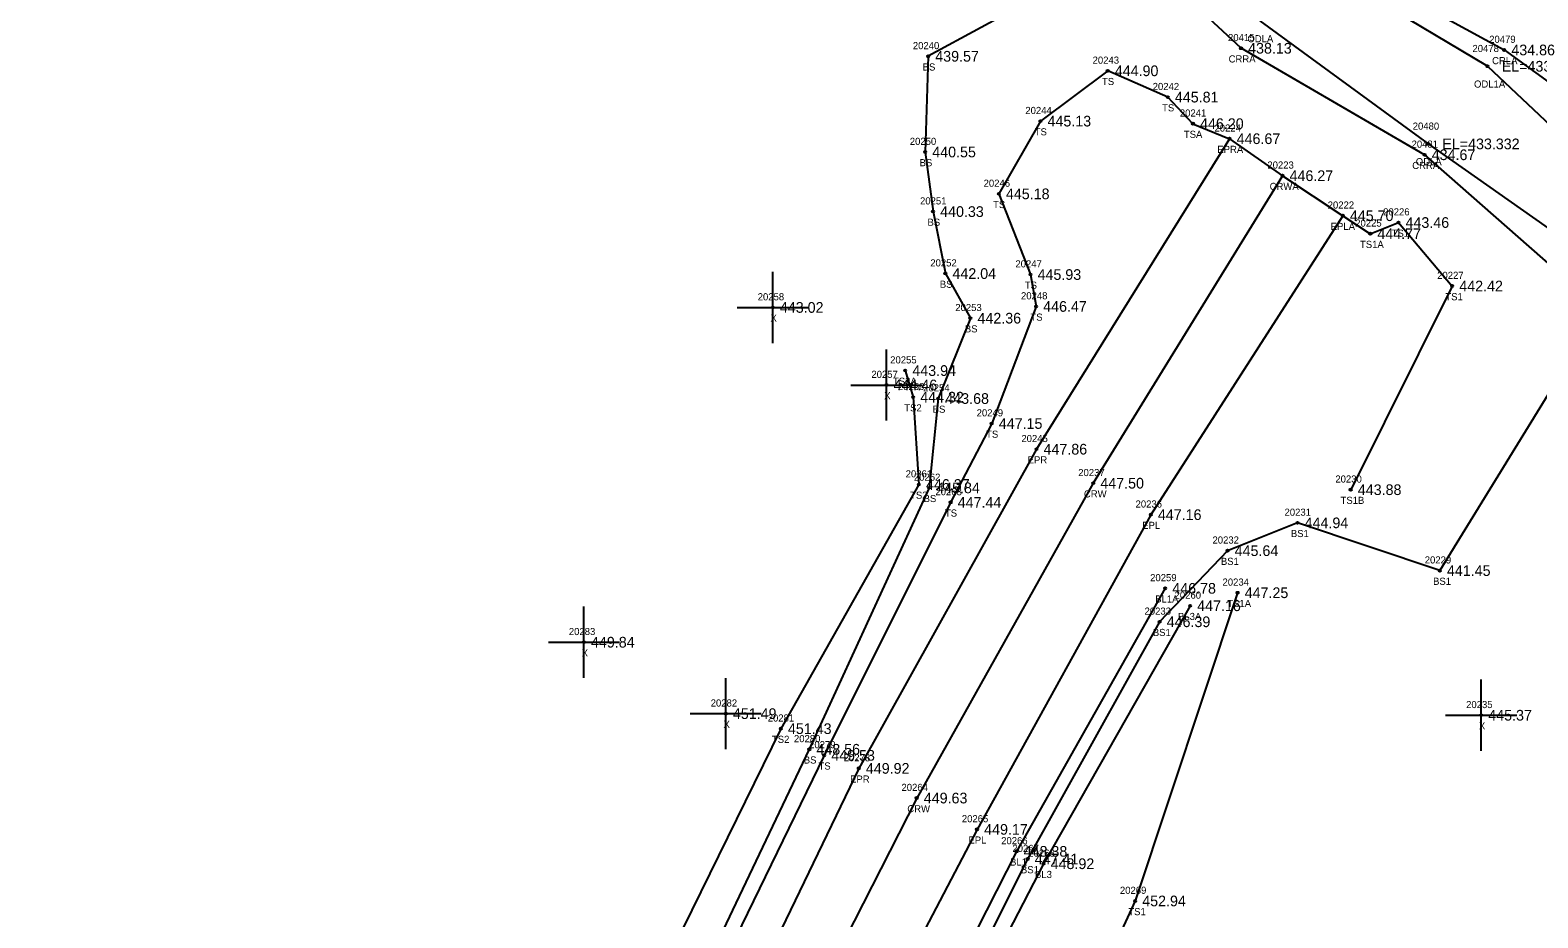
# Model space of a CAD drawing. Extents: x 1763022 to 1764007, y 824123 to 825394.
# Drawn here: x 1763289.5 to 1763501.5, y 824690.9 to 824815.6 of the extents above; entities that cross this region are included whole.
import ezdxf

# ---------------------------------------------------------------- set-up
doc = ezdxf.new("R2010")
doc.units = 0
for name, color, linetype in [('RD_DTM_BkLn1', 7, 'Continuous'), ('RD_DTM_BkLn2', 7, 'Continuous'), ('RD_DTM_BkLn_txCode', 7, 'Continuous'), ('RD_EX_H2O', 7, 'Continuous'), ('RD_EX_H2O_txCode', 7, 'Continuous'), ('RD_EX_Misc', 7, 'Continuous'), ('RD_EX_Misc_txCode', 7, 'Continuous'), ('RD_EX_Road', 7, 'Continuous'), ('RD_EX_Road_txCode', 7, 'Continuous'), ('RD_EX_TX_H2O_ELEV', 7, 'Continuous'), ('RD_EX_TX_Misc_ELEV', 7, 'Continuous'), ('RD_EX_TX_Road_ELEV', 7, 'Continuous'), ('RD_HC_Survey_ELEV', 7, 'Continuous'), ('RD_HC_Survey_txCode', 7, 'Continuous'), ('RD_SMD_Locator', 7, 'Continuous')]:
    doc.layers.add(name, color=color, linetype=linetype)

msp = doc.modelspace()

# ---------------------------------------------------------------- linework, layer by layer
at = {"layer": 'RD_DTM_BkLn1'}
for points in [[(1763465.6, 824795.18), (1763438.99, 824751.97), (1763414.16, 824707.73), (1763391.5, 824663.21), (1763370.27, 824618.19), (1763351.39, 824571.8), (1763333.36, 824525.39), (1763297, 824431.97), (1763261.49, 824337.79), (1763225.86, 824243.32), (1763189.96, 824148.95)], [(1763449.11, 824737.2), (1763428.21, 824700.24), (1763405.61, 824655.82), (1763384.69, 824612.58), (1763368.75, 824575.91)], [(1763452.61, 824734.75), (1763432, 824698.5), (1763409.25, 824654.57), (1763387.93, 824610.55), (1763372.47, 824573.42), (1763370.6, 824574.02), (1763368.75, 824575.91)]]:
    msp.add_lwpolyline(points, dxfattribs=at)
at = {"layer": 'RD_DTM_BkLn2'}
for points in [[(1763437.34, 824834), (1763430.66, 824820.06), (1763415.77, 824811.96), (1763415.35, 824798.51), (1763416.46, 824790.14), (1763418.19, 824781.43), (1763421.71, 824775.16), (1763417.19, 824763.87), (1763415.91, 824751.32), (1763399.06, 824714.58), (1763377.03, 824668.46), (1763355.81, 824623.79), (1763331.1, 824577.59), (1763312.25, 824532.84), (1763306.13, 824522.15), (1763306.75, 824510.59), (1763289.07, 824468.95), (1763279.57, 824438.1), (1763246.06, 824343.25), (1763209.87, 824247.25), (1763175.28, 824154.06)], [(1763453.01, 824802.49), (1763449.47, 824806.22), (1763441.02, 824809.92), (1763431.56, 824802.85), (1763425.71, 824792.63), (1763430.16, 824781.29), (1763430.95, 824776.81), (1763424.71, 824760.36), (1763418.93, 824749.28), (1763401.15, 824713.73), (1763378.81, 824667.77), (1763358.94, 824622.73), (1763337, 824576.46), (1763318.92, 824530.87), (1763314.75, 824518.63), (1763292.84, 824467.34), (1763282.85, 824437.24), (1763248.29, 824342.54), (1763211.77, 824246.85), (1763177.66, 824153.22)], [(1763477.95, 824787.03), (1763481.91, 824788.6), (1763489.47, 824779.68), (1763475.2, 824751.06)], [(1763510.31, 824776.41), (1763487.73, 824739.69), (1763467.72, 824746.4), (1763457.88, 824742.49), (1763448.32, 824732.5), (1763429.76, 824699.16), (1763407.64, 824655.12), (1763386.68, 824612.12), (1763370.96, 824575.87)], [(1763412.55, 824767.8), (1763413.66, 824764.06), (1763414.47, 824751.79), (1763395.05, 824717.48), (1763372.53, 824671.63), (1763352.41, 824624.78), (1763336.93, 824590.86)], [(1763459.29, 824736.58), (1763444.88, 824693.27), (1763423.62, 824647.11), (1763406.14, 824602.89), (1763396.88, 824581.15), (1763372.47, 824573.42)]]:
    msp.add_lwpolyline(points, dxfattribs=at)
at = {"layer": 'RD_EX_H2O'}
for p, q in [((1763469.64, 824827.68), (1763496.79, 824812.85)), ((1763494.44, 824810.56), (1763468.68, 824825.92)), ((1763462.4, 824816.93), (1763486.08, 824799.65)), ((1763485.59, 824798.12), (1763459.77, 824813.09))]:
    msp.add_line(p, q, dxfattribs=at)
for points in [[(1763459.77, 824813.09), (1763437.3, 824833.98), (1763421.73, 824846.89), (1763391.2, 824896.67), (1763313.16, 824962.88), (1763227.9, 824997.52), (1763208.46, 824998.22), (1763114.18, 824952.92), (1763092.86, 824935.95), (1763064.35, 824852.13)], [(1763496.79, 824812.85), (1763505.69, 824806.42), (1763507.16, 824805.23), (1763521.58, 824789.49), (1763543.54, 824765.51), (1763572.14, 824752.09), (1763662.42, 824704.48), (1763697.56, 824670.47), (1763707.93, 824630.76), (1763723.52, 824595.87), (1763766.82, 824582.67), (1763818.29, 824585.49), (1763920.08, 824604.11)], [(1763494.44, 824810.56), (1763519.46, 824787), (1763539.48, 824759.37), (1763565.01, 824743.23), (1763659.79, 824699.35), (1763693.94, 824667), (1763705.55, 824629.75), (1763723.44, 824593.51), (1763767.2, 824575.02), (1763820.02, 824582.79), (1763920.83, 824600.99)], [(1763486.08, 824799.65), (1763514.15, 824779.95), (1763533.52, 824748.31), (1763547.12, 824731.03), (1763648.42, 824679.07), (1763662.67, 824682.83), (1763683.5, 824662.48), (1763694.46, 824627.33), (1763694.82, 824601.41), (1763712.85, 824586.53), (1763766.86, 824564.42), (1763816.87, 824572.85), (1763926.33, 824585.82)], [(1763485.59, 824798.12), (1763510.28, 824776.41), (1763530.73, 824746.57), (1763546.51, 824728.76), (1763647.95, 824677.16), (1763661.46, 824680.21), (1763679.15, 824659.29), (1763688.38, 824626.34), (1763689.04, 824599.45), (1763710.73, 824574.27), (1763740.3, 824562), (1763762.69, 824555.26), (1763820.3, 824563.65), (1763926.69, 824582.3)]]:
    msp.add_lwpolyline(points, dxfattribs=at)
at = {"layer": 'RD_EX_Misc'}
for p, q in [((1763393.92, 824771.67), (1763393.92, 824781.67)), ((1763388.92, 824776.67), (1763398.92, 824776.67)), ((1763409.91, 824760.77), (1763409.91, 824770.77)), ((1763404.91, 824765.77), (1763414.91, 824765.77)), ((1763367.36, 824724.63), (1763367.36, 824734.63)), ((1763362.36, 824729.63), (1763372.36, 824729.63)), ((1763387.31, 824714.59), (1763387.31, 824724.59)), ((1763493.55, 824714.37), (1763493.55, 824724.37)), ((1763382.31, 824719.59), (1763392.31, 824719.59)), ((1763488.55, 824719.37), (1763498.55, 824719.37))]:
    msp.add_line(p, q, dxfattribs=at)
at = {"layer": 'RD_EX_Road'}
for points in [[(1763453.01, 824802.49), (1763458.16, 824800.38), (1763465.6, 824795.18), (1763474.08, 824789.56), (1763477.95, 824787.03)], [(1763458.16, 824800.38), (1763431, 824756.75), (1763406.01, 824711.9), (1763384.24, 824666.74), (1763362.81, 824620.84), (1763342.79, 824575), (1763324.89, 824528.78), (1763288.3, 824435.22), (1763252.09, 824341.05), (1763216.31, 824245.88), (1763180.37, 824152.33)], [(1763474.08, 824789.56), (1763447.08, 824747.55), (1763422.65, 824703.33), (1763399.6, 824659.26), (1763379.31, 824614.36), (1763364.49, 824579.4), (1763364.49, 824579.4), (1763359.36, 824568.52), (1763347.68, 824537.95), (1763341.79, 824522.26), (1763305.94, 824428.62), (1763270.17, 824334.76), (1763235.03, 824239.84), (1763198.43, 824144.73)]]:
    msp.add_lwpolyline(points, dxfattribs=at)
at = {"layer": 'RD_SMD_Locator'}
for centre in [(1763415.77, 824811.96), (1763459.77, 824813.09), (1763496.79, 824812.85), (1763441.02, 824809.92), (1763494.44, 824810.56), (1763449.47, 824806.22), (1763431.56, 824802.85), (1763453.01, 824802.49), (1763415.35, 824798.51), (1763458.16, 824800.38), (1763486.08, 824799.65), (1763485.59, 824798.12), (1763465.6, 824795.18), (1763425.71, 824792.63), (1763416.46, 824790.14), (1763474.08, 824789.56), (1763481.91, 824788.6), (1763477.95, 824787.03), (1763418.19, 824781.43), (1763430.16, 824781.29), (1763489.47, 824779.68), (1763393.92, 824776.67), (1763430.95, 824776.81), (1763421.71, 824775.16), (1763412.55, 824767.8), (1763409.91, 824765.77), (1763413.66, 824764.06), (1763417.19, 824763.87), (1763424.71, 824760.36), (1763431, 824756.75), (1763438.99, 824751.97), (1763414.47, 824751.79), (1763415.91, 824751.32), (1763475.2, 824751.06), (1763418.93, 824749.28), (1763447.08, 824747.55), (1763467.72, 824746.4), (1763457.88, 824742.49), (1763487.73, 824739.69), (1763449.11, 824737.2), (1763459.29, 824736.58), (1763452.61, 824734.75), (1763448.32, 824732.5), (1763367.36, 824729.63), (1763387.31, 824719.59), (1763493.55, 824719.37), (1763395.05, 824717.48), (1763399.06, 824714.58), (1763401.15, 824713.73), (1763406.01, 824711.9), (1763414.16, 824707.73), (1763422.65, 824703.33), (1763428.21, 824700.24), (1763429.76, 824699.16), (1763432, 824698.5), (1763444.88, 824693.27)]:
    msp.add_circle(centre, 0.15, dxfattribs=at)

# ---------------------------------------------------------------- texts
at = {"layer": 'RD_DTM_BkLn_txCode'}
for s, p in [('20240', (1763413.62, 824812.96)), ('20243', (1763438.9, 824810.92)), ('BS', (1763415, 824809.96)), ('TS', (1763440.22, 824807.92)), ('20242', (1763447.35, 824807.22)), ('TS', (1763448.67, 824804.22)), ('20244', (1763429.44, 824803.85)), ('20241', (1763451.17, 824803.49)), ('TS', (1763430.76, 824800.85)), ('TSA', (1763451.73, 824800.49)), ('20250', (1763413.19, 824799.51)), ('BS', (1763414.57, 824796.51)), ('20246', (1763423.57, 824793.63)), ('20251', (1763414.63, 824791.14)), ('TS', (1763424.91, 824790.63)), ('20226', (1763479.76, 824789.6)), ('BS', (1763415.68, 824788.14)), ('20225', (1763475.83, 824788.03)), ('TS1A', (1763476.5, 824785.03)), ('TS1', (1763480.95, 824786.6)), ('20252', (1763416.07, 824782.43)), ('20247', (1763428.04, 824782.29)), ('20227', (1763487.36, 824780.68)), ('BS', (1763417.41, 824779.43)), ('TS', (1763429.37, 824779.29)), ('20248', (1763428.83, 824777.81)), ('TS1', (1763488.51, 824777.68)), ('20253', (1763419.59, 824776.16)), ('TS', (1763430.16, 824774.81)), ('BS', (1763420.93, 824773.16)), ('20255', (1763410.43, 824768.8)), ('TS2A', (1763410.82, 824765.8)), ('20256', (1763411.51, 824765.06)), ('20254', (1763415.07, 824764.87)), ('TS2', (1763412.41, 824762.06)), ('BS', (1763416.41, 824761.87)), ('20249', (1763422.59, 824761.36)), ('TS', (1763423.92, 824758.36)), ('20261', (1763412.61, 824752.79)), ('20262', (1763413.77, 824752.32)), ('20230', (1763473.04, 824752.06)), ('TS2', (1763413.23, 824749.79)), ('BS', (1763415.13, 824749.32)), ('20263', (1763416.79, 824750.28)), ('TS1B', (1763473.77, 824749.06)), ('TS', (1763418.13, 824747.28)), ('20231', (1763465.89, 824747.4)), ('20232', (1763455.76, 824743.49)), ('BS1', (1763466.78, 824744.4)), ('BS1', (1763456.94, 824740.49)), ('20229', (1763485.61, 824740.69)), ('20259', (1763446.99, 824738.2)), ('20234', (1763457.17, 824737.58)), ('BS1', (1763486.78, 824737.69)), ('BL1A', (1763447.7, 824735.2)), ('20260', (1763450.43, 824735.75)), ('TS1A', (1763457.84, 824734.58)), ('20233', (1763446.2, 824733.5)), ('BL3A', (1763450.91, 824732.75)), ('BS1', (1763447.37, 824730.5)), ('20281', (1763393.21, 824718.48)), ('TS2', (1763393.8, 824715.48)), ('20280', (1763396.9, 824715.58)), ('20279', (1763399.03, 824714.73)), ('BS', (1763398.28, 824712.58)), ('TS', (1763400.35, 824711.73)), ('20266', (1763426.04, 824701.24)), ('20267', (1763427.62, 824700.16)), ('BL1', (1763427.29, 824698.24)), ('20268', (1763429.86, 824699.5)), ('BS1', (1763428.82, 824697.16)), ('BL3', (1763430.8, 824696.5)), ('20269', (1763442.74, 824694.27)), ('TS1', (1763443.92, 824691.27))]:
    msp.add_text(s, height=1, dxfattribs=at).set_placement(p)
at = {"layer": 'RD_EX_H2O_txCode'}
for s, p in [('20415', (1763457.94, 824814.09)), ('ODLA', (1763460.67, 824813.93)), ('20478', (1763492.32, 824812.56)), ('20479', (1763494.67, 824813.85)), ('CRRA', (1763458.03, 824811.09)), ('CRLA', (1763495.08, 824810.85)), ('ODL1A', (1763492.54, 824807.56)), ('20480', (1763483.92, 824801.65)), ('20481', (1763483.76, 824799.12)), ('CRRA', (1763483.85, 824796.12)), ('ODLA', (1763484.35, 824796.65))]:
    msp.add_text(s, height=1, dxfattribs=at).set_placement(p)
at = {"layer": 'RD_EX_Misc_txCode'}
for s, p in [('20258', (1763391.8, 824777.67)), ('X', (1763393.6, 824774.67)), ('20257', (1763407.79, 824766.77)), ('X', (1763409.59, 824763.77)), ('20283', (1763365.24, 824730.63)), ('X', (1763367.05, 824727.63)), ('20282', (1763385.19, 824720.59)), ('20235', (1763491.43, 824720.37)), ('X', (1763386.99, 824717.59)), ('X', (1763493.23, 824717.37))]:
    msp.add_text(s, height=1, dxfattribs=at).set_placement(p)
at = {"layer": 'RD_EX_Road_txCode'}
for s, p in [('20224', (1763456.04, 824801.38)), ('EPRA', (1763456.44, 824798.38)), ('20222', (1763471.96, 824790.56)), ('EPLA', (1763472.38, 824787.56)), ('20245', (1763428.88, 824757.75)), ('EPR', (1763429.77, 824754.75)), ('20236', (1763444.94, 824748.55)), ('EPL', (1763445.87, 824745.55)), ('20278', (1763403.9, 824712.9)), ('EPR', (1763404.79, 824709.9)), ('20265', (1763420.51, 824704.33)), ('EPL', (1763421.44, 824701.33))]:
    msp.add_text(s, height=1, dxfattribs=at).set_placement(p)
at = {"layer": 'RD_EX_TX_H2O_ELEV'}
for s, p in [('438.13', (1763460.77, 824812.34)), ('434.86', (1763497.79, 824812.1)), ('EL=433.437', (1763496.44, 824809.81)), ('434.67', (1763486.59, 824797.37)), ('EL=433.332', (1763488.08, 824798.9))]:
    msp.add_text(s, height=1.5, dxfattribs=at).set_placement(p)
at = {"layer": 'RD_EX_TX_Misc_ELEV'}
for s, p in [('439.57', (1763416.77, 824811.21)), ('444.90', (1763442.02, 824809.17)), ('445.81', (1763450.47, 824805.47)), ('445.13', (1763432.56, 824802.1)), ('446.20', (1763454.01, 824801.74)), ('440.55', (1763416.35, 824797.76)), ('445.18', (1763426.71, 824791.88)), ('440.33', (1763417.46, 824789.39)), ('443.46', (1763482.91, 824787.85)), ('444.77', (1763478.95, 824786.28)), ('442.04', (1763419.19, 824780.68)), ('445.93', (1763431.16, 824780.54)), ('442.42', (1763490.47, 824778.93)), ('443.02', (1763394.92, 824775.92)), ('446.47', (1763431.95, 824776.06)), ('442.36', (1763422.71, 824774.41)), ('443.94', (1763413.55, 824767.05)), ('444.46', (1763410.91, 824765.02)), ('444.32', (1763414.66, 824763.31)), ('443.68', (1763418.19, 824763.12)), ('447.15', (1763425.71, 824759.61)), ('446.37', (1763415.47, 824751.04)), ('445.84', (1763416.91, 824750.57)), ('447.44', (1763419.93, 824748.53)), ('443.88', (1763476.2, 824750.31)), ('444.94', (1763468.72, 824745.65)), ('445.64', (1763458.88, 824741.74)), ('441.45', (1763488.73, 824738.94)), ('446.78', (1763450.11, 824736.45)), ('447.25', (1763460.29, 824735.83)), ('447.16', (1763453.61, 824734)), ('446.39', (1763449.32, 824731.75)), ('449.84', (1763368.36, 824728.88)), ('451.49', (1763388.31, 824718.84)), ('451.43', (1763396.05, 824716.73)), ('445.37', (1763494.55, 824718.62)), ('448.56', (1763400.06, 824713.83)), ('449.53', (1763402.15, 824712.98)), ('448.38', (1763429.21, 824699.49)), ('447.41', (1763430.76, 824698.41)), ('448.92', (1763433, 824697.75)), ('452.94', (1763445.88, 824692.52))]:
    msp.add_text(s, height=1.5, dxfattribs=at).set_placement(p)
at = {"layer": 'RD_EX_TX_Road_ELEV'}
for s, p in [('446.67', (1763459.16, 824799.63)), ('445.70', (1763475.08, 824788.81)), ('447.86', (1763432, 824756)), ('447.16', (1763448.08, 824746.8)), ('449.92', (1763407.01, 824711.15)), ('449.17', (1763423.65, 824702.58))]:
    msp.add_text(s, height=1.5, dxfattribs=at).set_placement(p)
at = {"layer": 'RD_HC_Survey_ELEV'}
for s, p in [('446.27', (1763466.6, 824794.43)), ('447.50', (1763439.99, 824751.22)), ('449.63', (1763415.16, 824706.98))]:
    msp.add_text(s, height=1.5, dxfattribs=at).set_placement(p)
at = {"layer": 'RD_HC_Survey_txCode'}
for s, p in [('20223', (1763463.48, 824796.18)), ('CRWA', (1763463.8, 824793.18)), ('20237', (1763436.88, 824752.97)), ('CRW', (1763437.68, 824749.97)), ('20264', (1763412.02, 824708.73)), ('CRW', (1763412.84, 824705.73))]:
    msp.add_text(s, height=1, dxfattribs=at).set_placement(p)

doc.saveas('drawing.dxf')
